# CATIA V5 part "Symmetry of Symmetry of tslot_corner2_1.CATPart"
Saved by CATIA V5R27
Part number: Symmetry of Symmetry of tslot_corner2_1
Bounding box of the stored display mesh (mm): x -19.05 to 19.05, y -19.05 to 19.05, z -1374.764 to -1219.2
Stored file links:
  \\triton.meca.polymtl.ca\usagers\zaoue\profiles\Desktop\varm_ass\structure prismatique\Symmetry of Symmetry of tslot_corner2_1.CATPart
  \\triton.meca.polymtl.ca\usagers\zaoue\profiles\Desktop\varm_ass\structure prismatique\Symmetry of tslot_corner2_1.CATPart
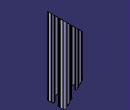
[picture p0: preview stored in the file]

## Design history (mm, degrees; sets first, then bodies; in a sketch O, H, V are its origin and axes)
Body1 (main body)
Body2 "Boss-Extrude1"
  Solid1: linked copy from another document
